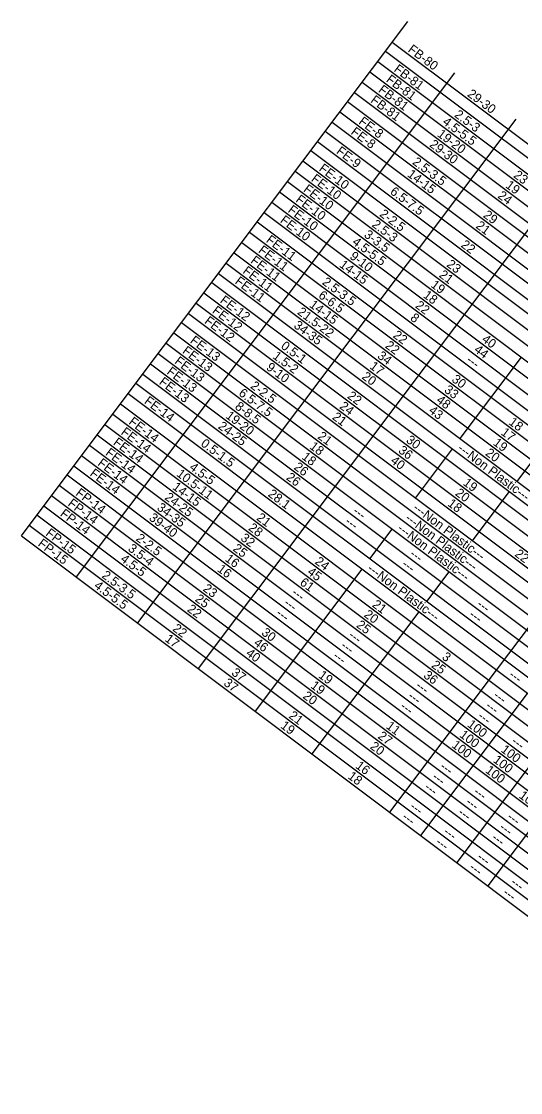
# Model space of a CAD drawing. Extents: x 627484.2 to 627514.4, y 367972.1 to 367996.9.
# Drawn here: x 627493.36 to 627496.37, y 367972.11 to 367978.58 of the extents above; entities that cross this region are included whole.
import ezdxf

# ---------------------------------------------------------------- set-up
doc = ezdxf.new("R2010")
doc.units = 0
doc.layers.add('Default', color=7, linetype='Continuous')

msp = doc.modelspace()

# ---------------------------------------------------------------- linework, layer by layer
at = {"layer": 'Default'}
for p, q in [((627494.0062, 367976.3314), (627495.6923, 367978.5769)), ((627495.5986, 367978.4521), (627500.0738, 367975.0916)), ((627495.5576, 367978.3975), (627500.0329, 367975.037)), ((627495.5108, 367978.3352), (627499.986, 367974.9747)), ((627494.3375, 367976.0826), (627495.9768, 367978.2657)), ((627495.4639, 367978.2728), (627499.9392, 367974.9123)), ((627495.4171, 367978.2104), (627499.8924, 367974.8499)), ((627495.3293, 367978.0935), (627499.8045, 367974.733)), ((627495.3703, 367978.1481), (627499.8455, 367974.7876)), ((627495.2825, 367978.0311), (627499.7577, 367974.6706)), ((627494.7079, 367975.8045), (627496.3471, 367977.9876)), ((627495.2356, 367977.9687), (627499.7109, 367974.6082)), ((627495.1946, 367977.9142), (627499.6699, 367974.5537)), ((627495.1478, 367977.8518), (627499.623, 367974.4913)), ((627495.1068, 367977.7972), (627499.5821, 367974.4367)), ((627495.06, 367977.7348), (627499.5352, 367974.3743)), ((627495.0743, 367975.5294), (627496.7136, 367977.7124)), ((627495.0131, 367977.6725), (627499.4884, 367974.312)), ((627494.9663, 367977.6101), (627499.4416, 367974.2496)), ((627494.9195, 367977.5477), (627499.3947, 367974.1872)), ((627494.8726, 367977.4853), (627499.3479, 367974.1248)), ((627494.8258, 367977.423), (627499.301, 367974.0625)), ((627494.7848, 367977.3684), (627499.2601, 367974.0079)), ((627494.738, 367977.306), (627499.2132, 367973.9455)), ((627494.6911, 367977.2437), (627499.1664, 367973.8831)), ((627494.6443, 367977.1813), (627499.1196, 367973.8208)), ((627494.5975, 367977.1189), (627499.0727, 367973.7584)), ((627494.5097, 367977.002), (627498.9849, 367973.6415)), ((627494.5506, 367977.0565), (627499.0259, 367973.696)), ((627494.4628, 367976.9396), (627498.9381, 367973.5791)), ((627494.416, 367976.8772), (627498.8912, 367973.5167)), ((627494.3691, 367976.8148), (627498.8444, 367973.4543)), ((627496.2282, 367974.6629), (627497.8675, 367976.846)), ((627494.3282, 367976.7603), (627498.8034, 367973.3998)), ((627494.2813, 367976.6979), (627498.7566, 367973.3374)), ((627494.2345, 367976.6355), (627498.7097, 367973.275)), ((627494.1877, 367976.5731), (627498.6629, 367973.2126)), ((627496.0087, 367976.0592), (627496.3775, 367976.5504)), ((627494.1408, 367976.5108), (627498.6161, 367973.1503)), ((627494.094, 367976.4484), (627498.5692, 367973.0879)), ((627494.053, 367976.3938), (627498.5282, 367973.0333)), ((627493.3622, 367975.4738), (627494.0062, 367976.3314)), ((627494.0062, 367976.3314), (627498.4814, 367972.9709)), ((627496.3517, 367975.8016), (627496.7205, 367976.2928)), ((627493.9593, 367976.2691), (627498.4346, 367972.9086)), ((627493.9125, 367976.2067), (627498.3877, 367972.8462)), ((627493.8657, 367976.1443), (627498.3409, 367972.7838)), ((627493.6935, 367975.225), (627494.3375, 367976.0826)), ((627493.8188, 367976.082), (627498.2941, 367972.7215)), ((627493.772, 367976.0196), (627498.2472, 367972.6591)), ((627495.7393, 367975.7006), (627495.9618, 367975.9969)), ((627493.6783, 367975.8948), (627498.1536, 367972.5343)), ((627493.7251, 367975.9572), (627498.2004, 367972.5967)), ((627493.6373, 367975.8403), (627498.1126, 367972.4798)), ((627493.5905, 367975.7779), (627498.0657, 367972.4174)), ((627494.0639, 367974.9469), (627494.7079, 367975.8045)), ((627493.5437, 367975.7155), (627498.0189, 367972.355)), ((627496.0824, 367975.443), (627496.3049, 367975.7393)), ((627493.4968, 367975.6531), (627497.9721, 367972.2926)), ((627493.4558, 367975.5986), (627497.9311, 367972.2381)), ((627493.409, 367975.5362), (627497.8842, 367972.1757)), ((627494.4303, 367974.6718), (627495.0743, 367975.5294)), ((627495.4642, 367975.3342), (627495.5988, 367975.5135)), ((627493.3622, 367975.4738), (627497.8374, 367972.1133)), ((627494.7733, 367974.4142), (627495.4173, 367975.2718)), ((627495.8072, 367975.0766), (627495.9419, 367975.2559)), ((627495.1164, 367974.1566), (627495.7604, 367975.0142)), ((627495.5842, 367973.8053), (627496.2282, 367974.6629)), ((627495.7713, 367973.6648), (627496.4153, 367974.5224)), ((627495.9896, 367973.5008), (627496.6336, 367974.3585)), ((627496.1767, 367973.3603), (627496.8207, 367974.218))]:
    msp.add_line(p, q, dxfattribs=at)

# ---------------------------------------------------------------- texts
for s, p in [('FB-80', (627495.6893, 367978.3984)), ('FB-81', (627495.6043, 367978.2793)), ('FB-81', (627495.5575, 367978.2169)), ('FB-81', (627495.5106, 367978.1546)), ('29-30', (627496.0474, 367978.1295)), ('FB-81', (627495.4638, 367978.0922)), ('2.5-3', (627495.9692, 367978.0053)), ('FE-8', (627495.3919, 367977.9633)), ('4.5-5.5', (627495.8975, 367977.9616)), ('FE-8', (627495.3451, 367977.9009)), ('19-20', (627495.8659, 367977.8878)), ('29-30', (627495.8191, 367977.8254)), ('FE-9', (627495.2568, 367977.7843)), ('FE-10', (627495.1525, 367977.6797)), ('2.5-3.5', (627495.716, 367977.7199)), ('FE-10', (627495.1057, 367977.6174)), ('14-15', (627495.6854, 367977.6454)), ('23', (627496.326, 367977.6399)), ('FE-10', (627495.0588, 367977.555)), ('6.5-7.5', (627495.5813, 367977.5406)), ('19', (627496.2778, 367977.5785)), ('FE-10', (627495.012, 367977.4926)), ('24', (627496.2307, 367977.5163)), ('FE-10', (627494.9652, 367977.4302)), ('FE-10', (627494.9183, 367977.3679)), ('2-2.5', (627495.5179, 367977.4054)), ('29', (627496.1432, 367977.3992)), ('3-3.5', (627495.4242, 367977.2806)), ('2.5-3', (627495.4716, 367977.3426)), ('21', (627496.0989, 367977.3348)), ('FE-11', (627494.8334, 367977.2488)), ('4.5-5.5', (627495.353, 367977.2366)), ('22', (627496.0085, 367977.2199)), ('FE-11', (627494.7865, 367977.1864)), ('9-10', (627495.3377, 367977.1505)), ('FE-11', (627494.7397, 367977.124)), ('14-15', (627495.2756, 367977.0996)), ('23', (627495.922, 367977.1019)), ('FE-11', (627494.6928, 367977.0617)), ('21', (627495.8765, 367977.0386)), ('FE-11', (627494.646, 367976.9993)), ('2.5-3.5', (627495.1715, 367976.9949)), ('19', (627495.827, 367976.9782)), ('6-6.5', (627495.149, 367976.9142)), ('18', (627495.7807, 367976.9154)), ('FE-12', (627494.5556, 367976.8843)), ('14-15', (627495.0941, 367976.8579)), ('22', (627495.7333, 367976.8534)), ('FE-12', (627494.4619, 367976.7596)), ('FE-12', (627494.5087, 367976.822)), ('21.5-22', (627495.0221, 367976.8144)), ('8', (627495.7032, 367976.7785)), ('34-35', (627495.0004, 367976.7332)), ('FE-13', (627494.3754, 367976.6416)), ('22', (627495.5987, 367976.6741)), ('40', (627496.1347, 367976.6496)), ('FE-13', (627494.3286, 367976.5792)), ('0.5-1', (627494.9226, 367976.6087)), ('22', (627495.5518, 367976.6117)), ('44', (627496.0878, 367976.5872)), ('FE-13', (627494.2817, 367976.5169)), ('1.5-2', (627494.8731, 367976.5483)), ('34', (627495.5048, 367976.5495)), ('---', (627496.0412, 367976.5247)), ('FE-13', (627494.2349, 367976.4545)), ('9-10', (627494.8342, 367976.48)), ('17', (627495.4583, 367976.4869)), ('FE-13', (627494.1881, 367976.3921)), ('20', (627495.4111, 367976.4248)), ('30', (627495.9532, 367976.4079)), ('6.5-7.5', (627494.668, 367976.3244)), ('2-2.5', (627494.7392, 367976.3684)), ('33', (627495.9079, 367976.3443)), ('FE-14', (627494.0987, 367976.2764)), ('22', (627495.3235, 367976.3077)), ('48', (627495.8602, 367976.2826)), ('19-20', (627494.5896, 367976.1882)), ('8-8.5', (627494.6456, 367976.2437)), ('24', (627495.2764, 367976.2455)), ('43', (627495.8142, 367976.2196)), ('FE-14', (627494.005, 367976.1516)), ('24-25', (627494.5437, 367976.125)), ('21', (627495.2325, 367976.181)), ('18', (627496.297, 367976.1498)), ('FE-14', (627493.9582, 367976.0892)), ('21', (627495.1446, 367976.064)), ('17', (627496.2497, 367976.0877)), ('FE-14', (627493.9113, 367976.0269)), ('0.5-1.5', (627494.4397, 367976.0203)), ('18', (627495.0957, 367976.0032)), ('30', (627495.678, 367976.0414)), ('19', (627496.2028, 367976.0254)), ('FE-14', (627493.8645, 367975.9645)), ('18', (627495.0488, 367975.9409)), ('36', (627495.6313, 367975.979)), ('---Non Plastic---', (627495.9883, 367975.9914)), ('20', (627496.1558, 367975.9632)), ('FE-14', (627493.8177, 367975.9021)), ('4.5-5', (627494.3704, 367975.8772)), ('26', (627495.0014, 367975.8789)), ('40', (627495.5844, 367975.9167)), ('FE-14', (627493.7708, 367975.8398)), ('10.5-11', (627494.2929, 367975.8379)), ('26', (627494.9546, 367975.8166)), ('14-15', (627494.2686, 367975.7586)), ('19', (627496.0213, 367975.7837)), ('FP-14', (627493.6848, 367975.7215)), ('24-25', (627494.2217, 367975.6962)), ('28.1', (627494.8451, 367975.7159)), ('20', (627495.9743, 367975.7215)), ('FP-14', (627493.5911, 367975.5967)), ('FP-14', (627493.6379, 367975.6591)), ('34-35', (627494.1749, 367975.6339)), ('---Non Plastic---', (627495.719, 367975.6327)), ('18', (627495.9281, 367975.6586)), ('39-40', (627494.1271, 367975.5722)), ('21', (627494.7758, 367975.5728)), ('---', (627495.3562, 367975.6125)), ('---Non Plastic---', (627495.6722, 367975.5703)), ('FP-15', (627493.5043, 367975.479)), ('28', (627494.7268, 367975.512)), ('---', (627495.3094, 367975.5501)), ('---Non Plastic---', (627495.6253, 367975.508)), ('FP-15', (627493.4575, 367975.4166)), ('2-2.5', (627494.0484, 367975.4484)), ('32', (627494.6795, 367975.45)), ('3.5-4', (627494.0005, 367975.3868)), ('25', (627494.6334, 367975.3871)), ('22', (627496.333, 367975.3545)), ('4.5-5', (627493.9547, 367975.3237)), ('16', (627494.5857, 367975.3254)), ('24', (627495.1277, 367975.3086)), ('---', (627495.6993, 367975.3549)), ('2.5-3.5', (627493.8425, 367975.225)), ('16', (627494.5389, 367975.263)), ('45', (627495.0819, 367975.2454)), ('---Non Plastic---', (627495.4438, 367975.2663)), ('---', (627495.6524, 367975.2925)), ('4.5-5.5', (627493.7957, 367975.1627)), ('61', (627495.0369, 367975.1817)), ('25', (627494.4051, 367975.083)), ('23', (627494.4525, 367975.145)), ('---', (627494.9874, 367975.1213)), ('22', (627494.3575, 367975.0212)), ('---', (627494.9405, 367975.0589)), ('21', (627495.4736, 367975.0488)), ('---', (627496.1047, 367975.0505)), ('---', (627494.8937, 367974.9966)), ('20', (627495.4239, 367974.9886)), ('---', (627496.0578, 367974.9881)), ('22', (627494.2697, 367974.9043)), ('25', (627495.3781, 367974.9255)), ('17', (627494.2229, 367974.8418)), ('30', (627494.8057, 367974.8797)), ('---', (627495.3304, 367974.8637)), ('46', (627494.759, 367974.8173)), ('---', (627495.2836, 367974.8013)), ('40', (627494.712, 367974.755)), ('---', (627495.2367, 367974.739)), ('3', (627495.894, 367974.7332)), ('37', (627494.6245, 367974.6378)), ('25', (627495.8303, 367974.6834)), ('37', (627494.5777, 367974.5755)), ('19', (627495.149, 367974.622)), ('36', (627495.7826, 367974.6217)), ('---', (627496.2975, 367974.6253)), ('19', (627495.1022, 367974.5596)), ('---', (627495.7358, 367974.5593)), ('20', (627495.0551, 367974.4974)), ('---', (627495.689, 367974.4969)), ('---', (627496.2038, 367974.5005)), ('21', (627494.9701, 367974.3783)), ('---', (627495.6422, 367974.4345)), ('---', (627496.157, 367974.4381)), ('19', (627494.9207, 367974.3179)), ('11', (627495.557, 367974.3156)), ('100', (627496.0469, 367974.3257)), ('---', (627496.1101, 367974.3758)), ('27', (627495.5077, 367974.2551)), ('100', (627496.0001, 367974.2633)), ('20', (627495.4605, 367974.193)), ('100', (627495.9532, 367974.201)), ('---', (627496.3128, 367974.2236)), ('100', (627496.2496, 367974.1735)), ('16', (627495.3728, 367974.0759)), ('---', (627495.8818, 367974.0717)), ('100', (627496.2028, 367974.1111)), ('18', (627495.3266, 367974.0131)), ('---', (627495.835, 367974.0093)), ('100', (627496.1559, 367974.0488)), ('---', (627495.7881, 367973.947)), ('---', (627496.0845, 367973.9195)), ('100', (627496.3586, 367973.8965)), ('---', (627495.7003, 367973.83)), ('---', (627496.0377, 367973.8571)), ('---', (627495.6535, 367973.7676)), ('---', (627495.9908, 367973.7947)), ('---', (627496.2872, 367973.7673)), ('---', (627496.2404, 367973.7049)), ('---', (627495.8562, 367973.6154)), ('---', (627495.903, 367973.6778)), ('---', (627496.1936, 367973.6425)), ('---', (627496.1057, 367973.5256)), ('---', (627496.0589, 367973.4632)), ('---', (627496.3085, 367973.3734)), ('---', (627496.2616, 367973.311))]:
    msp.add_text(s, height=0.055, rotation=323.09678, dxfattribs=at).set_placement(p)

doc.saveas('drawing.dxf')
